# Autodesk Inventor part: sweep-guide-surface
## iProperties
Created: 2006-01
Part Number: sweep-guide-surface
Document SubType Name: Modeling
Designer: CADCIM
Author: CADCIM
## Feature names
1. Extrusion1
